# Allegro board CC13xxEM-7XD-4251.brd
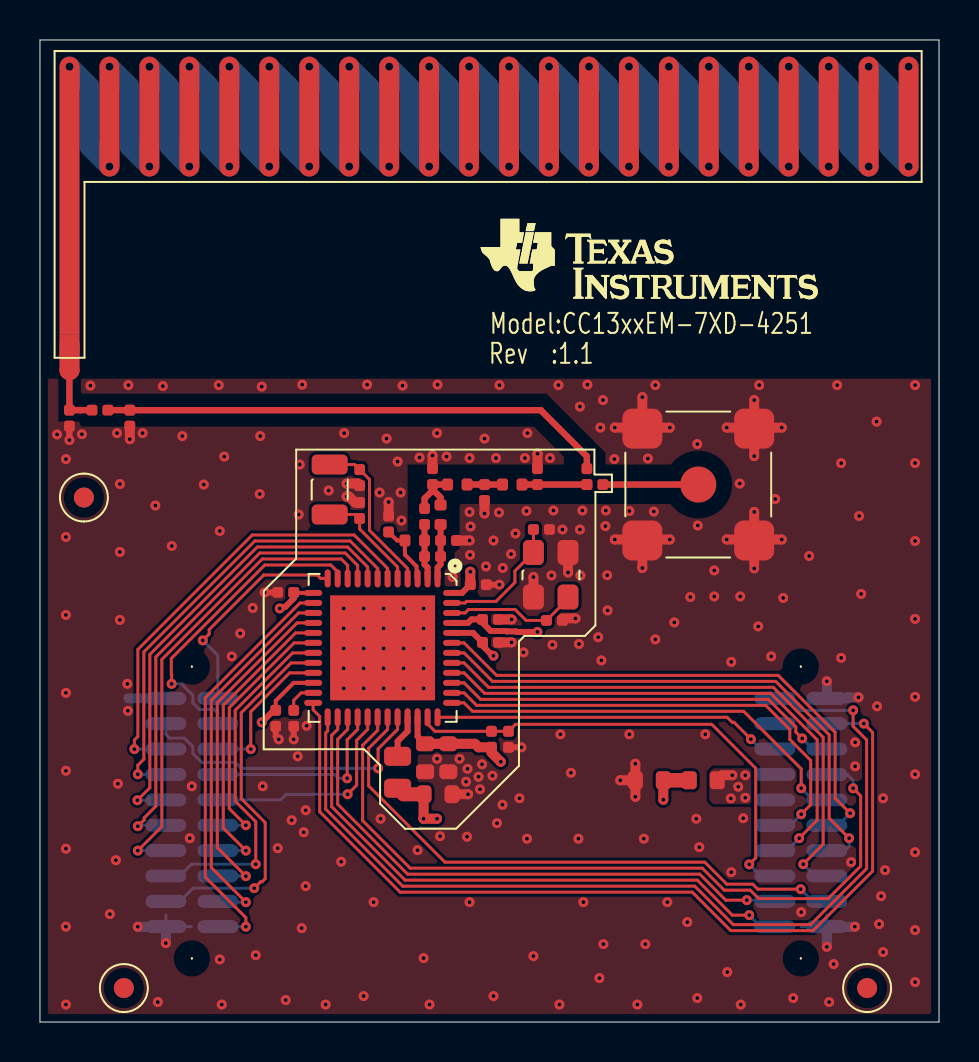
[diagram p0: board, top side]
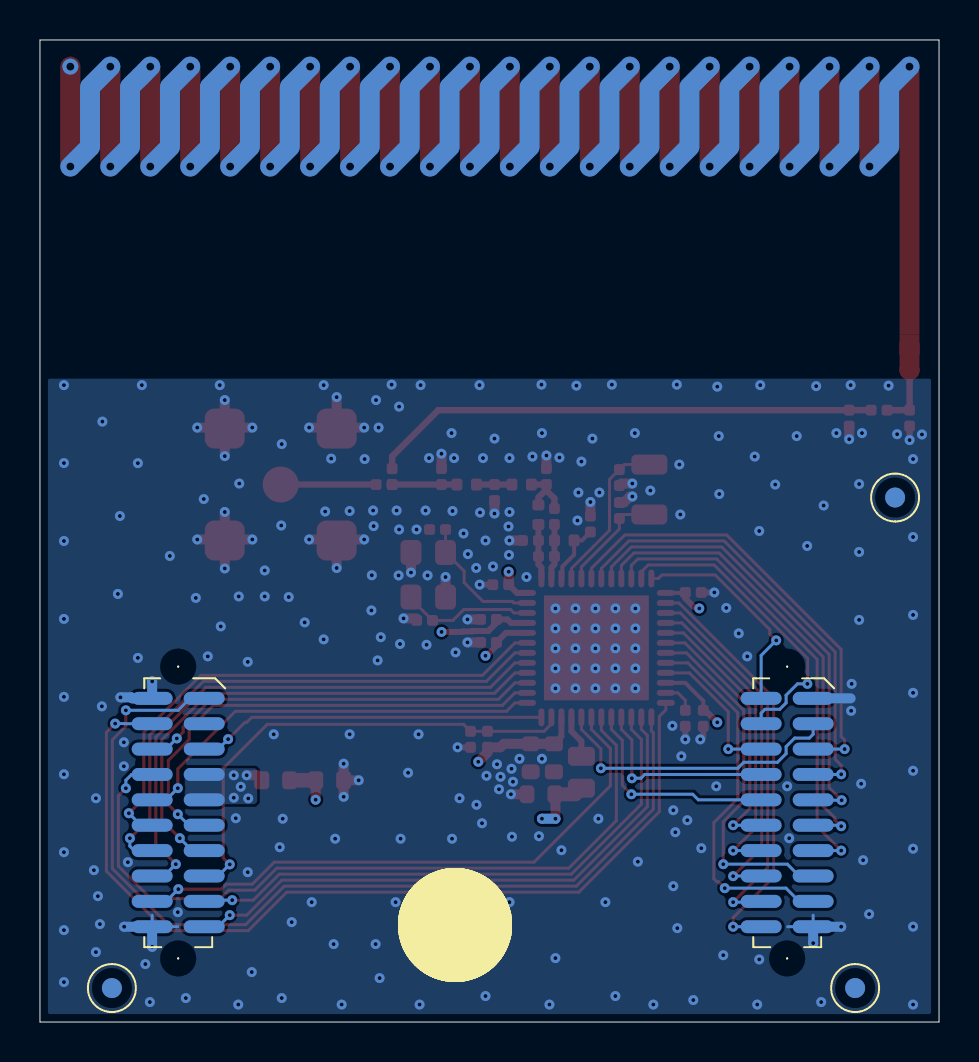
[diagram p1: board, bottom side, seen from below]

Outline 45 x 49.15 mm; copper layers: TOP, L2, L3, BOTTOM. Coordinates in mm from the lower left corner of the outline.
Outline path: 0,49.15 0,0 45,0 45,49.15 0,49.15

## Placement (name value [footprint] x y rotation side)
A1  Antenna PCB helix 433MHz  [ANTENNA_433MHZ_A2N]  1.48 33.89 0 top
C1  DNM  [CAPC1608X90L]  31.2 12.1 180 top
C11  8.2pF  [CAPC1005X60L]  20.05 24.1 0 top
C12  4.7pF  [CAPC1005X60L]  19.65 26.9 90 top
C13  12pF  [CAPC1005X60L]  22.25 26.1 90 top
C14  4.7pF  [CAPC1005X60L]  24.9 27.7 270 top
C15  330pF  [CAPC1005X60L]  28.17 26.9 180 top
C16  DNM_0402  [CAPC1005X60L]  27.37 27.7 270 top
C21  330pF  [CAPC1005X60L]  17.45 25.33 270 top
C22  8.2pF  [CAPC1005X60L]  19.25 24.9 90 top
C41  12pF  [CAPC1005X60L]  16 27.65 270 top
C51  12pF  [CAPC1005X60L]  16 25.2 90 top
C131  100nF  [CAPC1005X60L]  12.7 21.5 180 top
C221  100nF  [CAPC1005X60L]  11.8 15.6 270 top
C231  1uF  [CAPC1005X60L]  12.7 15.6 270 top
C331  22uF  [CAPC1608X100A2L]  19.22 11.4 0 top
C341  100nF  [CAPC1608X90L]  19.27 13.92 270 top
C342  22uF  [CAPC1608X100A2L]  20.44 13.93 270 top
C351  100nF  [CAPC1005X60L]  23.45 14.55 270 top
C441  100nF  [CAPC1005X60L]  22.15 19 0 top
C451  100nF  [CAPC1005X60L]  22.15 20.15 0 top
C461  DNM  [CAPC1005X60L]  25.35 20.1 0 top
C471  DNM  [CAPC1005X60L]  24.7 24.65 0 top
C481  100nF  [CAPC1005X60L]  21.54 21.89 0 top
FIDU1  FIDU_1MM  [FID100X115]  4.2 1.7 0 top
FIDU2  FIDU_1MM  [FID100X115]  41.4 1.7 0 top
FIDU3  FIDU_1MM  [FID100X115]  2.2 26.25 0 top
FIDU4  FIDU_1MM  [FID100X115]  4.2 1.7 180 bottom
FIDU5  FIDU_1MM  [FID100X115]  41.4 1.7 180 bottom
FIDU6  FIDU_1MM  [FID100X115]  2.2 26.25 180 bottom
FL1  BLM18HE152SN1  [FIL_BLM18HE152SN1DL]  32.5 12.1 0 top
J1  SMA-10V21-TGG  [HUSTSAN_SMA10V21TGGAN]  32.95 26.9 0 top
L11  33nH  [INDC1005X60L]  20.05 23.3 180 top
L12  15nH  [IND_LQW15AL]  20.05 24.9 90 top
L13  20nH  [IND_LQW15AL]  20.4 26.9 0 top
L14  20nH  [IND_LQW15AL]  23.15 26.9 0 top
L15  TBD  [INDC1005X60L]  4.5 30.62 270 top
L16  TBD  [INDC1005X60L]  1.47 30.62 270 top
L21  15nH  [IND_LQW15AL]  19.25 24.1 180 top
L331  6.8uH  [INDC2012X150L]  17.9 13.3 270 top
NOREF  -  []  0 40.68 0 top
NOREF#2  -  []  34.66 0 90 top
NOREF#3  -  []  23.05 40.2 0 top
NOREF#4  -  []  27.4 1.83 180 bottom
P1  SFM-110-02-S-D-A-K-TR  [SAMTEC_SFM11002AN]  6.3 16.2 0 bottom
P2  SFM-110-02-S-D-A-K-TR  [SAMTEC_SFM11002AN]  36.78 16.2 0 bottom
R13  0  [RESC1005X40L]  2.6 30.62 0 top
R351  100k  [RESC1005X40L]  22.6 14.55 270 top
U1  CC13xx 7x7  [QFNFC50P700X700X80-49CN]  19.9 22.2 180 top
Y1  32.768kHz  [XTAL_FC-135N]  14.5 27.9 270 top
Y2  24MHz  [OSCCC250X320X60-4L]  24.7 23.5 270 top

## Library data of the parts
A1 = ANTENNA: User Part Number: #PN
C1 C341 = CAPACITOR: alternate symbols: (CAPC1608X90L,CAPC1608X90M)
C11 C22 = CAPACITOR: alternate symbols: (CAPC1005X60M,CAPC1005X60L)
C12-C16 C21 C41 C51 C131 C221 C231 C351 C441 C451 C461 C471 C481 = CAPACITOR: alternate symbols: (CAPC1005X60L,CAPC1005X60M)
C331 C342 = CAPACITOR: User Part Number: #PN; alternate symbols: (CAPC1608X100A2L,CAPC1608X100A2M)
FIDU1-FIDU6 = FIDMARK
FL1 = FILTER_2PIN: alternate symbols: (FIL_BLM18HE152SN1DL,FIL_BLM18HE152SN1DM)
J1 = CONN_COAX_1+4: alternate symbols: (HUSTSAN_SMA10V21TGGL,HUSTSAN_SMA10V21TGGM)
L11 = INDUCTOR: alternate symbols: (INDC1005X60L,INDC1005X60M)
L12 L21 = INDUCTOR: alternate symbols: (IND_LQW15AM,IND_LQW15AL)
L13 L14 = INDUCTOR: alternate symbols: (IND_LQW15AL,IND_LQW15AM)
L15 L16 = INDUCTOR: alternate symbols: (INDC1005X60M,INDC1005X60L)
L331 = INDUCTOR: alternate symbols: (INDC2012X150L,INDC2012X150M)
P1 P2 = CONN_HEADER_2X10_P_S
R13 R351 = RESISTOR: alternate symbols: (RESC1005X40L,RESC1005X40M)
U1 = IC_RF_CC13XX_7X7_QFN48_V2: alternate symbols: (QFNFC50P700X700X80-49CL,QFNFC50P700X700X80-49CM)
Y1 = CRYSTAL: alternate symbols: (XTAL_FC-135L,XTAL_FC-135M)
Y2 = XTAL_4PIN_S: alternate symbols: (OSCCC250X320X60-4L,OSCCC250X320X60-4M)

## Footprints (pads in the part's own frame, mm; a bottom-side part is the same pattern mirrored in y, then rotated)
ANTENNA_433MHZ_A2N
  rect 1x1 smd: 1(0,0)
CAPC1005X60L
  custom 0.135x0.135 smd: 1(0,0) 2(0.8,0)
CAPC1608X90L
  custom 0.188x0.188 smd: 1(0,0) 2(1.4,0)
CAPC1608X100A2L
  custom 0.188x0.188 smd: 1(0,0) 2(1.4,0)
FID100X115
  oval 1x1 smd: 1(0,0)
FIL_BLM18HE152SN1DL
  custom 0.188x0.188 smd: 1(0,0) 2(1.4,0)
HUSTSAN_SMA10V21TGGAN
  round 1.801 smd: 1(0,0)
  custom 0.5x0.5 smd: 2(-2.8,-2.8) 3(2.8,-2.8) 4(2.8,2.8) 5(-2.8,2.8)
IND_LQW15AL
  custom 0.138x0.138 smd: 1(0,0) 2(0.98,0)
INDC1005X60L
  custom 0.135x0.135 smd: 1(0,0) 2(0.8,0)
INDC2012X150L
  custom 0.237x0.237 smd: 1(0,0) 2(1.6,0)
OSCCC250X320X60-4L
  custom 0.263x0.263 smd: 1(0,0) 2(2.23,0) 3(2.23,1.73) 4(0,1.73)
QFNFC50P700X700X80-49CN
  oval 0.3x0.9 smd: 1(0,0) 2(0.5,0) 3(1,0) 4(1.5,0) 5(2,0) 6(2.5,0) 7(3,0) 8(3.5,0) 9(4,0) 10(4.5,0) 11(5,0) 12(5.5,0) 25(5.5,6.95) 26(5,6.95) 27(4.5,6.95) 28(4,6.95) 29(3.5,6.95) 30(3,6.95) 31(2.5,6.95) 32(2,6.95) 33(1.5,6.95) 34(1,6.95) 35(0.5,6.95) 36(0,6.95)
  oval 0.9x0.3 smd: 13(6.225,0.725) 14(6.225,1.225) 15(6.225,1.725) 16(6.225,2.225) 17(6.225,2.725) 18(6.225,3.225) 19(6.225,3.725) 20(6.225,4.225) 21(6.225,4.725) 22(6.225,5.225) 23(6.225,5.725) 24(6.225,6.225) 37(-0.725,6.225) 38(-0.725,5.725) 39(-0.725,5.225) 40(-0.725,4.725) 41(-0.725,4.225) 42(-0.725,3.725) 43(-0.725,3.225) 44(-0.725,2.725) 45(-0.725,2.225) 46(-0.725,1.725) 47(-0.725,1.225) 48(-0.725,0.725)
  rect 5.25x5.25 smd: 49(2.75,3.475)
RESC1005X40L
  custom 0.135x0.135 smd: 1(0,0) 2(0.8,0)
SAMTEC_SFM11002AN
  round 0.099 hole 1.501 unplated: (1.302,-1.588) (1.302,13.017)
  oval 2.05x0.65 smd: 1(0,0) 2(2.604,0) 3(0,1.27) 4(2.604,1.27) 5(0,2.54) 6(2.604,2.54) 7(0,3.81) 8(2.604,3.81) 9(0,5.08) 10(2.604,5.08) 11(0,6.35) 12(2.604,6.35) 13(0,7.62) 14(2.604,7.62) 15(0,8.89) 16(2.604,8.89) 17(0,10.16) 18(2.604,10.16) 19(0,11.43) 20(2.604,11.43)
XTAL_FC-135N
  custom 0.25x0.25 smd: 1(0,0) 2(2.5,0)

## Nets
GND: C1.2 C11.2 C12.2 C13.1 C14.1 C21.1 C41.2 C51.2 C131.2 C221.2 C231.2 C331.2 C341.2 C342.2 C351.2 C441.2 C451.2 C461.2 C471.2 C481.2 J1.2 J1.3 J1.4 J1.5 L15.2 L16.2 P1.1 P1.19 P2.2 P2.20 U1.49(VSS) Y2.2 Y2.4
VDD_EB: FL1.2 P2.7 P2.9
VDDR: C331.1 C451.1 C481.1 L331.2 U1.45(VDDR#45) U1.48(VDDR#48)
VDDS: C1.1 C131.1 C221.1 C341.1 C342.1 C441.1 FL1.1 R351.2 U1.13(VDDS2) U1.22(VDDS3) U1.34(VDDS_DCDC) U1.44(VDDS)
DCDC_SW: L331.1 U1.33(DCDC_SW)
DIO_1: P1.5 U1.6(DIO_1)
DIO_2: P1.7 U1.7(DIO_2)
DIO_3: P1.9 U1.8(DIO_3)
DIO_4: P1.11 U1.9(DIO_4)
DIO_5: P1.13 U1.10(DIO_5)
DIO_6: P1.4 U1.11(DIO_6)
DIO_7: P1.2 U1.12(DIO_7)
DIO_8: P1.20 U1.14(DIO_8)
DIO_9: P1.18 U1.15(DIO_9)
DIO_10: P1.16 U1.16(DIO_10)
DIO_11: P1.14 U1.17(DIO_11)
DIO_12: P1.12 U1.18(DIO_12)
DIO_13: P1.15 U1.19(DIO_13)
DIO_14: P1.17 U1.20(DIO_14)
DIO_15: P1.6 U1.21(DIO_15)
DIO_16 / JTAG TDO: P2.19 U1.26(DIO_16)
DIO_17 / JTAG TDI: P2.17 U1.27(DIO_17)
DIO_18: P1.8 U1.28(DIO_18)
DIO_19: P1.10 U1.29(DIO_19)
DIO_20: P2.8 U1.30(DIO_20)
DIO_21: P2.18 U1.31(DIO_21)
DIO_22: P1.3 U1.32(DIO_22)
DIO_23: P2.5 U1.36(DIO_23)
DIO_24: P2.10 U1.37(DIO_24)
DIO_25: P2.11 U1.38(DIO_25)
DIO_26: P2.6 U1.39(DIO_26)
DIO_27: P2.13 U1.40(DIO_27)
DIO_28: P2.16 U1.41(DIO_28)
DIO_29: P2.14 U1.42(DIO_29)
DIO_30: P2.12 U1.43(DIO_30)
JTAG_TCK: P2.1 U1.25(JTAG_TCKC)
JTAG_TMS: P2.4 U1.24(JTAG_TMSC)
NRESET: C351.1 P2.15 R351.1 U1.35(RESET_N)
N485531: C15.1 J1.1
N485535: A1.1(FEED/GND_1) L16.1 R13.1
N485571: C461.1 U1.46(X24M_N) Y2.3
N485643: C22.1 L11.2 L21.1 U1.2(RF_N)
N485645: C11.1 L11.1 L12.1 U1.1(RF_P)
N485661: C12.1 C22.2 L12.2 L13.1
N485675: C13.2 L13.2 L14.1
N485699: C231.1 U1.23(DCOUPL)
N485701: C41.1 U1.4(X32K_Q1) Y1.1
N485707: C51.1 U1.5(X32K_Q2) Y1.2
N485827: C14.2 C15.2 C16.2 L14.2
N485901: C16.1 L15.1 R13.2
N485927: C21.2 L21.2 U1.3(RX_TX)
N485953: C471.1 U1.47(X24M_P) Y2.1

Pads without a net: FIDU1 1; FIDU2 1; FIDU3 1; FIDU4 1; FIDU5 1; FIDU6 1; P2 3

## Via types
v1: diameter 0.5, hole 0.2, TOP to BOTTOM, 316 vias
v2: diameter 0.8, hole 0.4, TOP to BOTTOM, 43 vias

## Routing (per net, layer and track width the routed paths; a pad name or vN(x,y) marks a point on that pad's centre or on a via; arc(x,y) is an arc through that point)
GND: length 49.1
  TOP w0.15: U1.49 17.17,18.73 v1(17.2,18.7)
  TOP w0.3: v1(22.99,21.89) C481.2 ; C131.2 v1(11.25,21.5) ; C351.2 v1(24.1,13.75) ; C221.2 11.8,14.3 11.95,14.15 v1(11.95,14.15) ; v1(12.7,14.15) C231.2
  TOP w0.32: L16.2 v1(1.47,29.12)
  TOP w0.5: 20.67,11.4 v1(21.43,11.4) ; C1.2 v1(29.8,12.93) ; C1.2 v1(29.05,12.1) ; C1.2 v1(29.8,11.27) ; 35.75,24.15 v1(34.37,24.15) ; 35.75,24.15 v1(37.13,24.15) ; 35.75,24.15 v1(35.75,25.53) ; 35.75,24.15 J1.3 35.75,22.9 ; 26.43,23.6 Y2.4 v1(26.43,22.5) ; C51.2 15.77,26 15.47,26.3 v1(15.35,26.3) ; v1(28.77,29.75) 30.15,29.75 ; 30.15,29.75 v1(30.15,31.28) ; 30.15,29.75 v1(31.53,29.75) ; C441.2 v1(23.6,19) ; v1(15.35,26.95) 15.9,26.95 C41.2 ; v1(34.37,29.75) 35.75,29.75 ; 35.75,29.75 v1(35.75,31.13) ; 35.75,29.75 J1.4 v1(35.75,28.32) ; 35.75,29.75 v1(37.13,29.75) ; C12.2 v1(19.65,28.35) ; 26.15,20.2 v1(26.8,20.2) ; v1(24.91,28.44) 24.9,28.44 C14.1 ; 24.7,21.37 v1(24.7,22.27) ; C13.1 v1(22.25,25.45) ; 30.15,24.15 v1(28.77,24.15) ; 30.15,24.15 J1.2 v1(30.15,22.72) ; 30.15,24.15 v1(31.53,24.15) ; C21.1 v1(17.45,26.03) ; C451.2 v1(23.6,20.15) ; L15.2 v1(4.5,29.17) ; C11.2 v1(21.5,24.1)
  BOTTOM w0.15: 40.38,16.2 40.66,16.2 ; 6.3,5.35 P1.19 7.58,4.77 ; 39.38,5.35 P2.20 38.11,4.77
  BOTTOM w0.5: v1(6.3,3.95) P1.19 v1(4.9,4.77) ; v1(40.79,4.77) P2.20 v1(39.38,3.77) ; v1(40.97,16.25) 40.43,16.25 40.38,16.2 P2.2 v1(39.38,17.05) ; P1.1 4.42,16.2
  vias: v1(0.86,29.41) v1(1.3,28.17) v1(1.3,24.28) v1(1.3,20.38) v1(1.3,16.48) v1(1.3,12.58) v1(1.3,8.67) v1(1.3,4.78) v1(1.3,0.88) v1(2.1,29.42) v1(2.52,31.85) v1(3.5,5.4) v1(3.8,8.1) v1(3.86,29.48) v1(3.9,11.92) v1(4,26.92) v1(4,23.53) v1(4,20.12) v1(4.42,31.88) v1(4.38,16.92) v1(4.4,15.58) v1(5.14,29.48) v1(5.77,25.85) v1(5.9,1) v1(6.15,31.83) v1(6.6,23.83) v1(7.12,29.33) v1(7.5,9.2) v1(7.6,11.8) v1(8.2,26.9) v1(8.95,31.88) v1(9,24.58) v1(9,3.13) v1(9.1,0.88) v1(9.22,28.3) v1(9.6,18.3) v1(10.02,19.45) v1(10.65,20.73) v1(10.8,3.34) v1(11.02,29.33) v1(11,26.42) v1(11.1,31.8) v1(11.15,11.8) v1(11.9,8.7) v1(12.3,1.1) v1(12.6,10.1) v1(12.9,13.3) v1(13,27.9) v1(12.95,25.4) v1(13.12,31.9) v1(13.1,4.7) v1(13.2,9.5) v1(13.35,14.83) v1(13.3,10.6) v1(13.3,6.8) v1(14.3,0.88) v1(14.45,26.6) v1(15.08,8.03) v1(15.22,29.48) v1(15.2,20.7) v1(15.2,19.7) v1(15.2,18.7) v1(15.2,17.7) v1(15.2,16.7) v1(16.2,20.7) v1(16.2,19.7) v1(16.2,18.7) v1(16.2,17.7) v1(16.2,16.7) v1(16.2,1.3) v1(16.38,31.9) v1(16.7,6) v1(17,26.5) v1(17.05,10.17) v1(17.2,20.7) v1(17.2,19.7) v1(17.2,17.7) v1(17.2,16.7) v1(17.35,29.2) v1(17.9,28.05) v1(18.15,31.85) v1(18.05,26.5) v1(18.1,25.1) v1(18.2,20.7) v1(18.2,19.7) v1(18.2,18.7) v1(18.2,17.7) v1(18.2,16.7) v1(18.9,8.6) v1(19,28.25) v1(19.2,20.7) v1(19.2,19.7) v1(19.2,18.7) v1(19.2,17.7) v1(19.2,16.7) v1(19.2,3.2) v1(19.5,0.88) v1(19.9,31.9) v1(19.88,29.48) v1(19.88,13.17) v1(20.02,9.3) v1(20.35,28.3) v1(20.65,22.28) v1(21,13.17) v1(21.33,12.03) v1(21.4,12.67) v1(21.38,9.28) v1(21.5,28.23) v1(21.5,25.53) v1(21.55,24.8) v1(21.52,23.38) v1(21.5,6) v1(21.95,12.28) v1(22.02,11.65) v1(22.12,12.9) v1(22.25,29.2) v1(22.33,22.8) v1(22.65,12.33) v1(22.7,24.1) v1(22.7,1.3) v1(22.83,28.23) v1(22.88,9.95) v1(23,31.88) v1(22.97,25.5) v1(23.17,22.73) v1(23.15,10.87) v1(23.58,23.42) v1(23.8,24.45) v1(24,11.2) v1(24.2,18.5) v1(24.27,28.23) v1(24.4,29.48) v1(24.35,25.58) v1(24.37,9.17) v1(24.7,3.3) v1(25.53,28.23) v1(25.6,22.35) v1(25.65,18.88) v1(25.7,25.6) v1(25.95,31.88) v1(26,0.88) v1(26.05,14.4) v1(26.15,24.65) v1(26.58,12.48) v1(27.02,30.8) v1(27.02,24.65) v1(26.98,18.92) v1(26.95,9.17) v1(27.15,25.6) v1(27.05,22.35) v1(27.2,6) v1(27.4,31.9) v1(27.94,19.26) v1(28,2.2) v1(28.05,29.75) v1(28.1,18.1) v1(28.18,31.13) v1(28.2,3.9) v1(28.33,25.6) v1(28.3,24.82) v1(28.39,22.36) v1(28.41,20.6) v1(28.75,28.17) v1(29.5,25.58) v1(29.5,14.4) v1(29.9,0.88) v1(30.23,9.17) v1(30.3,3.9) v1(30.42,28.2) v1(30.73,25.55) v1(30.8,31.88) v1(30.8,19.15) v1(31.4,6) v1(31.75,20) v1(32.4,5) v1(32.55,21.27) v1(32.9,28.92) v1(32.92,24.85) v1(32.85,10.17) v1(32.9,1.2) v1(33,8.75) v1(33.3,14.4) v1(33.75,22.6) v1(33.75,21.3) v1(34.4,2.5) v1(34.6,18.03) v1(34.6,7.5) v1(35.02,26.95) v1(35.05,21.3) v1(35.08,0.88) v1(35.2,10.2) v1(35.75,22.7) v1(36,31.88) v1(35.95,19.8) v1(36.6,18.3) v1(36.8,26.17) v1(37.2,21.23) v1(37.7,1.2) v1(38.1,5.5) v1(38.5,23.33) v1(39.5,1) v1(39.73,2.9) v1(39.9,31.88) v1(40.1,27.97) v1(40.1,18.23) v1(40.6,8) v1(40.8,14) v1(40.8,12.8) v1(41,25.33) v1(41.1,21.42) v1(41.87,30.05) v1(41.9,15.8) v1(42,4.9) v1(42.1,6.3) v1(42.2,11.2) v1(42.2,3.5) v1(42.3,7.6) v1(43.8,31.88) v1(43.8,27.98) v1(43.8,24.08) v1(43.8,20.17) v1(43.8,16.28) v1(43.8,12.4) v1(43.8,8.5) v1(43.8,4.6) v1(43.8,2)
VDD_EB: length 0.9
  TOP w0.5: FL1.2 34.15,12.35 v1(34.65,12.35)
  vias: v1(34.58,11.19) v1(34.95,11.78) v1(35.3,12.35) v1(35.3,11.23)
VDDR: length 29
  TOP w0.3: C481.1 21.12,21.48 U1.48 ; v1(24.9,19.53) 23.86,19.53 23.83,19.55 23.37,19.55 23.35,19.57 22.56,19.57 22.15,19.98 C451.1 21.6,20.15 21.42,19.98 U1.45
  TOP w0.5: v1(19.88,10.17) v1(19.2,10.17) 19.2,11.38 C331.1 ; v1(21.54,22.54) C481.1
  TOP w0.7: L331.2 18.2,11.4 C331.1
  L2 w0.5: v1(19.2,10.17) v1(19.88,10.17)
  L3 w0.5: v1(21.54,22.54) 22.2,21.88 22.2,21.76 22.72,21.24 23.43,21.24 24.9,19.77 v1(24.9,19.53) 24.9,13.54 21.53,10.17 v1(19.88,10.17) v1(19.2,10.17)
  BOTTOM w0.5: v1(19.2,10.17) v1(19.88,10.17)
VDDS: length 65.9
  TOP w0.2: C131.1 12.72,21.48 U1.13 ; C221.1 11.8,16.08 12.7,16.98 U1.22
  TOP w0.3: v1(22.7,18.33) 22.58,18.45 22.53,18.45 22.15,18.83 C441.1 21.67,19.48 U1.44 ; v1(12,20.7) 12.07,20.77 12.27,20.77 12.7,21.2 C131.1 ; v1(11.1,15) 11.7,15.6 C221.1 ; C341.1 18.9,14.3 U1.34
  TOP w0.5: v1(23.06,13.03) 22.6,13.49 R351.2 21.95,13.75 21.78,13.93 C342.1 20.44,13.92 C341.1 ; v1(31.2,11.12) C1.1
  TOP w0.73: FL1.1 C1.1
  L3 w0.5: v1(12,20.7) 11.1,19.8 v1(11.1,15) 11.1,14.08 17.3,7.88 18.25,7.88 ; v1(31.2,11.12) 31.2,9.23 29.85,7.88 18.25,7.88 ; 18.71,14.34 21.75,14.34 v1(23.06,13.03) ; 18.71,14.34 v1(22.7,18.33) ; 18.71,14.34 18.25,13.88 18.25,7.88
DCDC_SW: length 2.2
  TOP w0.3: U1.33 18.4,14.55 17.9,14.05 L331.1
DIO_1: length 22.7
  TOP w0.15: v1(4.72,13.66) 4.72,14.11 4.9,14.29 4.9,18.65 10.63,24.38 15.73,24.38 17.4,22.7 U1.6
  BOTTOM w0.15: v1(4.72,13.66) P1.5
DIO_2: length 22.7
  TOP w0.15: U1.7 16.9,22.7 15.52,24.08 10.75,24.08 5.2,18.52 5.2,13.15 4.9,12.85 v1(4.9,12.4)
  BOTTOM w0.15: P1.7 5.11,12.39 5.1,12.4 v1(4.9,12.4)
DIO_3: length 23.1
  TOP w0.15: v1(4.88,11.1) 5.5,11.73 5.5,18.4 10.88,23.78 15.4,23.78 16.4,22.78 U1.8
  BOTTOM w0.15: P1.9 6.28,11.1 v1(4.88,11.1)
DIO_4: length 23.4
  TOP w0.15: U1.9 15.9,22.85 15.27,23.48 11,23.48 5.8,18.27 5.8,10.8 5.22,10.22 5.22,10.12 v1(4.9,9.8)
  BOTTOM w0.15: v1(4.9,9.8) 4.95,9.8 5,9.85 P1.11
DIO_5: length 23.6
  TOP w0.15: v1(4.9,8.58) 6.1,9.78 6.1,18.15 11.13,23.17 15.08,23.17 15.4,22.85 U1.10
  BOTTOM w0.15: P1.13 v1(4.9,8.58)
DIO_6: length 15.7
  TOP w0.15: v1(6.59,16.92) 6.59,17.38 6.58,17.39 6.58,18.2 11.25,22.88 14.56,22.88 14.9,22.53 U1.11
  BOTTOM w0.15: P1.4 8.9,15.46 8.71,15.65 7.98,15.65 7.65,15.97 7.65,16.36 7.08,16.92 v1(6.59,16.92)
DIO_7: length 11
  TOP w0.15: v1(8.15,19.1) 8.47,19.42 8.47,19.64 11.2,22.38 13.87,22.38 14.05,22.2 U1.12
  BOTTOM w0.15: P1.2 8.9,18.35 v1(8.15,19.1)
DIO_8: length 21.1
  TOP w0.15: U1.14 13.02,20.98 8.27,16.23 8.27,7.25 10.31,5.22 v1(10.31,4.77)
  BOTTOM w0.15: P1.20 v1(10.31,4.77)
DIO_9: length 19.2
  TOP w0.15: U1.15 12.94,20.48 8.58,16.11 8.58,7.73 v1(10.31,6)
  BOTTOM w0.15: v1(10.31,6) 8.94,6 P1.18
DIO_10: length 17.1
  TOP w0.15: v1(10.31,7.3) 8.88,8.73 8.88,15.98 12.87,19.98 U1.16
  BOTTOM w0.15: v1(10.31,7.3) 10.14,7.3 10.13,7.31 P1.16
DIO_11: length 15.1
  TOP w0.15: v1(10.31,8.58) 9.17,9.71 9.17,15.86 12.79,19.48 U1.17
  BOTTOM w0.15: v1(10.31,8.58) P1.14
DIO_12: length 13.2
  TOP w0.15: v1(10.31,9.85) 9.47,10.68 9.47,15.73 12.72,18.98 U1.18
  BOTTOM w0.15: v1(10.31,9.85) P1.12
DIO_13: length 18
  TOP w0.15: U1.19 12.64,18.48 9.77,15.61 9.77,11.05 10.8,10.03 v1(10.8,7.9)
  BOTTOM w0.15: v1(10.8,7.9) 7.59,7.9 7,7.31 P1.15
DIO_14: length 18.9
  TOP w0.15: v1(10.72,6.7) 11.05,7.02 11.12,7.02 11.27,7.17 11.27,9.98 10.08,11.18 10.08,15.48 12.57,17.98 U1.20
  BOTTOM w0.15: P1.17 7,6.04 7.66,6.7 v1(10.72,6.7)
DIO_15: length 7.4
  TOP w0.15: v1(10.55,13.66) 10.55,15.53 12.49,17.48 U1.21
  BOTTOM w0.15: P1.6 v1(10.55,13.66)
DIO_16 / JTAG TDO: length 29.3
  TOP w0.15: U1.26 14.9,14.65 14.6,14.35 14.6,10.78 18.28,7.1 32.9,7.1 34.65,5.35 v1(35.5,5.35)
  BOTTOM w0.15: v1(35.5,5.35) 36.08,4.77 P2.19
DIO_17 / JTAG TDI: length 28.4
  TOP w0.15: U1.27 15.4,14.65 14.9,14.15 14.9,10.9 18.4,7.4 33.02,7.4 34.33,6.1 v1(35.38,6.1)
  BOTTOM w0.15: P2.17 36.08,6.04 36.02,6.1 v1(35.38,6.1)
DIO_18: length 9.8
  TOP w0.15: v1(15.38,12.2) 15.38,14.12 15.9,14.65 U1.28
  BOTTOM w0.15: v1(15.38,12.2) 14.92,12.2 14.73,12.39 P1.8
DIO_19: length 10.9
  TOP w0.15: v1(15.4,11.4) 15.85,11.85 15.85,14.1 16.4,14.65 U1.29
  BOTTOM w0.15: P1.10 12.05,11.12 12.33,11.4 v1(15.4,11.4)
DIO_20: length 38.6
  TOP w0.15: v1(40.7,11.7) 41.08,11.33 41.08,7.8 39.45,6.17 35.98,6.17 35.55,6.6 34.25,6.6 33.15,7.7 18.53,7.7 16.15,10.08 16.15,13.85 16.9,14.6 U1.30
  BOTTOM w0.15: v1(40.7,11.7) 40.7,12.1 40.41,12.39 P2.8
DIO_21: length 29.2
  TOP w0.15: v1(38.07,6.65) 35.92,6.65 35.67,6.9 34.37,6.9 33.27,8 20.27,8 16.45,11.82 16.45,13.7 17.4,14.65 U1.31
  BOTTOM w0.15: P2.18 38.68,6.04 v1(38.07,6.65)
DIO_22: length 15
  TOP w0.15: U1.32 17.9,14.65 16.92,13.67 v1(16.92,12.7)
  BOTTOM w0.15: v1(16.92,12.7) 10.07,12.7 9.77,13 8.09,13 7.65,13.43 7.65,13.78 7.23,14.21 6.49,14.21 6.3,14.4 P1.3
DIO_23: length 17.5
  TOP w0.15: v1(35.58,14.16) 34.74,15 34.65,15 34.4,15.25 U1.36
  BOTTOM w0.15: P2.5 36.08,13.66 v1(35.58,14.16)
DIO_24: length 21.3
  TOP w0.15: v1(38.1,11.7) 38.1,12.67 35.22,15.55 21.65,15.55 21.23,15.98 U1.37
  BOTTOM w0.15: P2.10 38.68,11.12 v1(38.1,11.7)
DIO_25: length 24.1
  TOP w0.15: U1.38 21.23,16.48 21.85,15.85 36.33,15.85 37.53,14.64 37.53,14.14 38.58,13.1 38.58,10.88 v1(38.1,10.4)
  BOTTOM w0.15: v1(38.1,10.4) 37.55,9.85 P2.11
DIO_26: length 20.3
  TOP w0.15: U1.39 21.23,16.98 22.05,16.15 36.45,16.15 37.83,14.77 37.83,14.51 v1(38.15,14.19)
  BOTTOM w0.15: P2.6 38.68,13.66 v1(38.15,14.19)
DIO_27: length 26.4
  TOP w0.15: v1(38,9.2) 38.9,10.1 38.9,14.12 36.58,16.45 22.25,16.45 21.23,17.48 U1.40
  BOTTOM w0.15: P2.13 37.38,8.58 v1(38,9.2)
DIO_28: length 28.3
  TOP w0.15: v1(38.2,7.9) 39.2,8.9 39.2,14.25 36.7,16.75 22.45,16.75 21.23,17.98 U1.41
  BOTTOM w0.15: v1(38.2,7.9) 38.8,7.3 39.37,7.3 P2.16
DIO_29: length 27.8
  TOP w0.15: v1(40.5,9.2) 39.5,10.2 39.5,14.38 36.82,17.05 22.65,17.05 21.23,18.48 U1.42
  BOTTOM w0.15: v1(40.5,9.2) 40.5,8.8 40.28,8.58 P2.14
DIO_30: length 26.8
  TOP w0.15: v1(40.55,10.45) 39.8,11.2 39.8,14.5 36.95,17.35 22.85,17.35 21.23,18.98 U1.43
  BOTTOM w0.15: v1(40.55,10.45) 39.95,9.85 P2.12
JTAG_TCK: length 47.6
  TOP w0.15: U1.25 14.4,14.57 14.3,14.47 14.3,10.65 18.15,6.8 32.77,6.8 34.7,4.88 38.57,4.88 41.37,7.68 41.37,14.12 40.7,14.8 v1(40.7,15.6)
  BOTTOM w0.15: v1(40.7,15.6) 38.08,15.6 37.48,16.2 P2.1
JTAG_TMS: length 46.4
  TOP w0.15: v1(41.24,14.94) 41.67,14.5 41.67,7.55 38.7,4.58 34.58,4.58 32.65,6.5 18.03,6.5 14,10.53 14,15.3 13.67,15.62 U1.24
  BOTTOM w0.15: P2.4 40.78,14.93 40.78,14.94 v1(41.24,14.94)
Net_61:
  vias: v2(1.48,47.82) v2(3.48,42.82)
Net_62:
  vias: v2(41.48,47.82) v2(43.48,47.82) v2(43.48,42.82)
Net_63:
  vias: v2(39.48,47.82) v2(41.48,42.82)
Net_64:
  vias: v2(37.48,47.82) v2(39.48,42.82)
Net_65:
  vias: v2(35.48,47.82) v2(37.48,42.82)
Net_66:
  vias: v2(33.48,47.82) v2(35.48,42.82)
Net_67:
  vias: v2(31.48,47.82) v2(33.48,42.82)
Net_68:
  vias: v2(29.48,47.82) v2(31.48,42.82)
Net_69:
  vias: v2(27.48,47.82) v2(29.48,42.82)
Net_70:
  vias: v2(25.48,47.82) v2(27.48,42.82)
Net_71:
  vias: v2(23.48,47.82) v2(25.48,42.82)
Net_72:
  vias: v2(21.48,47.82) v2(23.48,42.82)
Net_73:
  vias: v2(19.48,47.82) v2(21.48,42.82)
Net_74:
  vias: v2(17.48,47.82) v2(19.48,42.82)
Net_75:
  vias: v2(15.48,47.82) v2(17.48,42.82)
Net_76:
  vias: v2(13.48,47.82) v2(15.48,42.82)
Net_77:
  vias: v2(11.48,47.82) v2(13.48,42.82)
Net_78:
  vias: v2(9.48,47.82) v2(11.48,42.82)
Net_79:
  vias: v2(7.48,47.82) v2(9.48,42.82)
Net_80:
  vias: v2(5.48,47.82) v2(7.48,42.82)
Net_81:
  vias: v2(3.48,47.82) v2(5.48,42.82)
NRESET: length 24.4
  TOP w0.15: v1(35.5,7.89) 35.83,8.22 35.83,12.7 33.62,14.9 23.8,14.9 C351.1 R351.1 19.77,14.55 19.4,14.92 U1.35
  BOTTOM w0.15: P2.15 36.08,7.31 v1(35.5,7.89)
N485531: length 4.8
  TOP w0.32: C15.1 J1.1
N485535: length 4.4
  TOP w0.32: 1.47,32.62 L16.1 2.03,30.62 2.03,30.62 R13.1
  TOP w1: A1.1 1.48,32.63 1.47,32.62
N485571: length 6.6
  TOP w0.15: U1.46 21.28,20.48 21.45,20.64 23.78,20.64 24.33,20.1 C461.1 26.43,21.18 Y2.3
N485643: length 2.8
  TOP w0.3: C22.1 19.25,24.9 L21.1 19.25,24.1 L11.2 19.25,22.9 19.4,22.75 U1.2
N485645: length 2.8
  TOP w0.3: L12.1 20.05,24.1 C11.1 L11.1 20.05,22.9 19.9,22.75 U1.1
N485661: length 3.1
  TOP w0.3: 20.05,26.25 20.05,26.25 L12.2 ; 19.65,26.65 C12.1
  TOP w0.32: C12.1 L13.1 ; 20.05,26.25 19.65,26.65 19.65,26.6 19.25,26.2 C22.2
N485675: length 1.8
  TOP w0.32: L13.2 C13.2 L14.1
N485699: length 1.6
  TOP w0.15: C231.1 12.7,16.1 13.07,16.48 U1.23
N485701: length 8
  TOP w0.15: Y1.1 15.75,27.9 C41.1 16.49,27.16 16.49,24.61 18.4,22.7 U1.4
N485707: length 5.4
  TOP w0.15: U1.5 17.9,22.78 16,24.67 C51.1 15.8,25.4 Y1.2
N485827: length 3.2
  TOP w0.32: L14.2 C14.2 C15.2
N485901: length 25.5
  TOP w0.32: C16.1 27.37,28.31 25.06,30.62 25.06,30.62 L15.1 4.5,30.62 R13.2
N485927: length 3.2
  TOP w0.2: U1.3 18.85,22.25 18.85,22.8 18.27,23.38 L21.2 17.87,24.1 C21.2
N485953: length 6.6
  TOP w0.15: C471.1 Y2.1 23.77,22.57 23.77,22 22.82,21.05 21.35,21.05 21.28,20.98 U1.47

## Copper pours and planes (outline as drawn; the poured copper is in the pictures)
GND on TOP: 0.4,0.4 0.4,32.2 0.92,32.2 0.92,30.05 2,30.05 2,29.9 2.1,29.8 24.73,29.8 26.23,28.3 26.23,27.9 18.4,27.9 18.4,23 18.3,22.9 13.9,22.9 13.5,22.5 13.5,15.75 14,15.25 21,15.25 21,25.92 31.57,25.92 34.64,26.88 31.58,27.9 28.3,27.9 28.3,28.5 25.35,31.45 2.05,31.45 2.05,32.2 44.6,32.2 44.6,0.4 ; 6 cut-outs
GND on TOP: 21.15,23.8 20.75,23.51 20.75,23 20.25,22.59 20.25,21.88 20.31,21.8 21.05,21.8 21.05,23.1 21.58,23.62
GND on BOTTOM: 0.4,0.4 0.4,32.2 44.6,32.2 44.6,0.4 ; 8 cut-outs
GND on L2, L3: 0.4,0.4 0.4,32.2 44.6,32.2 44.6,0.4
VDD_EB on TOP: 33.7,12.7 35.5,12.7 35.7,12.5 35.7,11.1 35.5,10.9 33.7,10.9 33.5,11.1 33.5,12.5
VDD_EB on BOTTOM: 34.23,12.7 37.5,12.7 37.75,12.45 37.75,11.05 37.6,10.9 34.25,10.9 34.12,11.03 34.12,12.6
Net_61 on BOTTOM (solid shape): 1.13,47.46 1.13,48.17 1.83,48.17 2.85,47.16 2.96,46.99 2.99,46.8 2.99,44.01 3.83,43.17 3.83,42.46 3.12,42.46 2.14,43.45 2.03,43.61 1.99,43.8 1.99,46.59
Net_62 on BOTTOM (solid shape): 41.13,47.46 41.13,48.17 41.83,48.17 42.85,47.16 42.95,46.99 42.99,46.8 42.99,44.01 43.83,43.17 43.83,42.46 43.12,42.46 42.14,43.45 42.03,43.61 41.99,43.8 41.99,46.59
Net_63 on BOTTOM (solid shape): 39.13,47.46 39.13,48.17 39.83,48.17 40.85,47.16 40.95,46.99 40.99,46.8 40.99,44.01 41.83,43.17 41.83,42.46 41.12,42.46 40.14,43.45 40.03,43.61 39.99,43.8 39.99,46.59
Net_64 on BOTTOM (solid shape): 37.13,47.46 37.13,48.17 37.83,48.17 38.85,47.16 38.95,46.99 38.99,46.8 38.99,44.01 39.83,43.17 39.83,42.46 39.12,42.46 38.14,43.45 38.03,43.61 37.99,43.8 37.99,46.59
Net_65 on BOTTOM (solid shape): 35.13,47.46 35.13,48.17 35.83,48.17 36.85,47.16 36.95,46.99 36.99,46.8 36.99,44.01 37.83,43.17 37.83,42.46 37.12,42.46 36.14,43.45 36.03,43.61 35.99,43.8 35.99,46.59
Net_66 on BOTTOM (solid shape): 33.13,47.46 33.13,48.17 33.83,48.17 34.85,47.16 34.95,46.99 34.99,46.8 34.99,44.01 35.83,43.17 35.83,42.46 35.12,42.46 34.14,43.45 34.03,43.61 33.99,43.8 33.99,46.59
Net_67 on BOTTOM (solid shape): 31.13,47.46 31.13,48.17 31.83,48.17 32.85,47.16 32.95,46.99 32.99,46.8 32.99,44.01 33.83,43.17 33.83,42.46 33.12,42.46 32.14,43.45 32.03,43.61 31.99,43.8 31.99,46.59
Net_68 on BOTTOM (solid shape): 29.13,47.46 29.13,48.17 29.83,48.17 30.85,47.16 30.95,46.99 30.99,46.8 30.99,44.01 31.83,43.17 31.83,42.46 31.12,42.46 30.14,43.45 30.03,43.61 29.99,43.8 29.99,46.59
Net_69 on BOTTOM (solid shape): 27.13,47.46 27.13,48.17 27.83,48.17 28.85,47.16 28.95,46.99 28.99,46.8 28.99,44.01 29.83,43.17 29.83,42.46 29.12,42.46 28.14,43.45 28.03,43.61 27.99,43.8 27.99,46.59
Net_70 on BOTTOM (solid shape): 25.13,47.46 25.13,48.17 25.83,48.17 26.85,47.16 26.95,46.99 26.99,46.8 26.99,44.01 27.83,43.17 27.83,42.46 27.12,42.46 26.14,43.45 26.03,43.61 25.99,43.8 25.99,46.59
Net_71 on BOTTOM (solid shape): 23.13,47.46 23.13,48.17 23.83,48.17 24.85,47.16 24.96,46.99 24.99,46.8 24.99,44.01 25.83,43.17 25.83,42.46 25.12,42.46 24.14,43.45 24.03,43.61 23.99,43.8 23.99,46.59
Net_72 on BOTTOM (solid shape): 21.13,47.46 21.13,48.17 21.83,48.17 22.85,47.16 22.95,46.99 22.99,46.8 22.99,44.01 23.83,43.17 23.83,42.46 23.12,42.46 22.14,43.45 22.03,43.61 21.99,43.8 21.99,46.59
Net_73 on BOTTOM (solid shape): 19.13,47.46 19.13,48.17 19.83,48.17 20.85,47.16 20.95,46.99 20.99,46.8 20.99,44.01 21.83,43.17 21.83,42.46 21.12,42.46 20.14,43.45 20.03,43.61 19.99,43.8 19.99,46.59
Net_74 on BOTTOM (solid shape): 17.13,47.46 17.13,48.17 17.83,48.17 18.85,47.16 18.95,46.99 18.99,46.8 18.99,44.01 19.83,43.17 19.83,42.46 19.12,42.46 18.14,43.45 18.03,43.61 17.99,43.8 17.99,46.59
Net_75 on BOTTOM (solid shape): 15.12,47.46 15.12,48.17 15.83,48.17 16.84,47.16 16.95,46.99 16.99,46.8 16.99,44.01 17.83,43.17 17.83,42.46 17.12,42.46 16.14,43.45 16.03,43.61 15.99,43.8 15.99,46.59
Net_76 on BOTTOM (solid shape): 13.12,47.46 13.13,48.17 13.83,48.17 14.85,47.16 14.95,46.99 14.99,46.8 14.99,44.01 15.83,43.17 15.83,42.46 15.12,42.46 14.14,43.45 14.03,43.61 13.99,43.8 13.99,46.59
Net_77 on BOTTOM (solid shape): 11.12,47.46 11.12,48.17 11.83,48.17 12.84,47.16 12.95,46.99 12.99,46.8 12.99,44.01 13.83,43.17 13.83,42.46 13.12,42.46 12.14,43.45 12.03,43.61 11.99,43.8 11.99,46.59
Net_78 on BOTTOM (solid shape): 9.12,47.46 9.12,48.17 9.83,48.17 10.85,47.16 10.95,46.99 10.99,46.8 10.99,44.01 11.83,43.17 11.83,42.46 11.12,42.46 10.14,43.45 10.03,43.61 9.99,43.8 9.99,46.59
Net_79 on BOTTOM (solid shape): 7.13,47.46 7.13,48.17 7.83,48.17 8.85,47.16 8.95,46.99 8.99,46.8 8.99,44.01 9.83,43.17 9.83,42.46 9.12,42.46 8.14,43.45 8.03,43.61 7.99,43.8 7.99,46.59
Net_80 on BOTTOM (solid shape): 5.12,47.46 5.12,48.17 5.83,48.17 6.84,47.16 6.95,46.99 6.99,46.8 6.99,44.01 7.83,43.17 7.83,42.46 7.12,42.46 6.14,43.45 6.03,43.61 5.99,43.8 5.99,46.59
Net_81 on BOTTOM (solid shape): 3.12,47.46 3.13,48.17 3.83,48.17 4.85,47.16 4.95,46.99 4.99,46.8 4.99,44.01 5.83,43.17 5.83,42.46 5.12,42.46 4.14,43.45 4.03,43.61 3.99,43.8 3.99,46.59

Small or netless copper shapes (teardrops, artwork), in the pictures only: 22 on TOP

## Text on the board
Ref Des/Silkscreen Top: Rev  :1.1 | Model:CC13xxEM-7XD-4251
XSECTION_CHART: *  SURFACE - AIR 0 MM | L1: TOP CONDUCTOR - COPPER 0.035 MM | *  DIELECTRIC - FR-4 0.175 MM | L2: L2 PLANE - COPPER 0.018 MM | *  DIELECTRIC - FR-4 1.14 MM | L3: L3 PLANE - COPPER 0.018 MM | L4: BOTTOM CONDUCTOR - COPPER 0.035 MM | DESIGN CROSS SECTION CHART | ___________________________ | TOTAL THICKNESS 1.596 MM
NCLEGEND-1-4: FIGURE | SIZE | 0.2 | 0.4 | 1.501 | DRILL CHART: TOP to BOTTOM | ALL UNITS ARE IN MILLIMETERS | PLATED | NON-PLATED | QTY | 291 | 25 | 43 | 4
